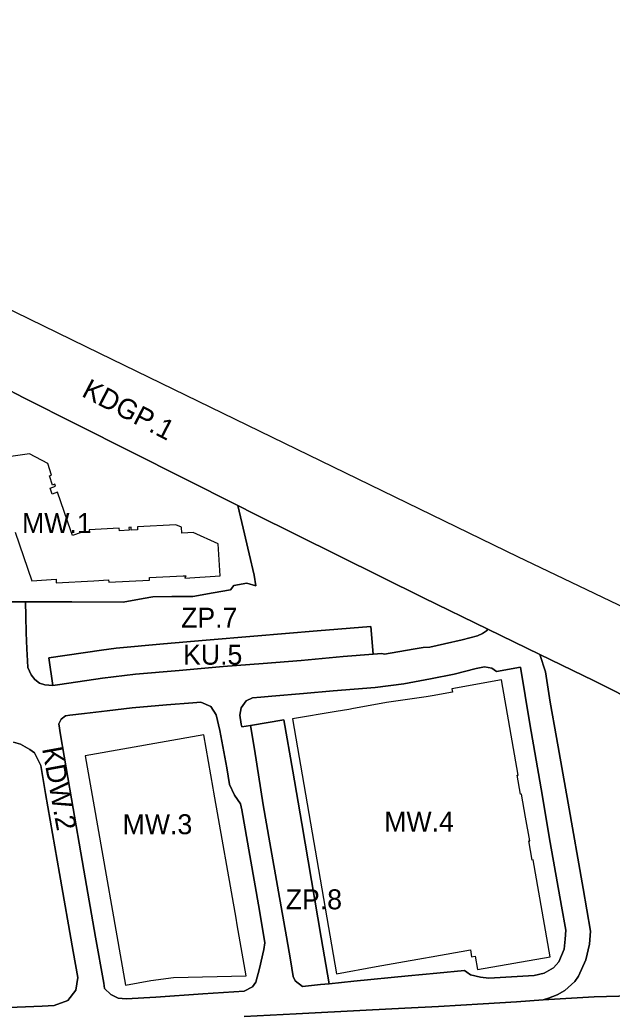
# Model space of a CAD drawing. Extents: x 7429178 to 7430831, y 5550228 to 5551611.
# Drawn here: x 7430079.5 to 7430227.9, y 5551215.2 to 5551464.4 of the extents above; entities that cross this region are included whole.
import ezdxf

# ---------------------------------------------------------------- set-up
doc = ezdxf.new("R2010")
doc.units = 0
for name, color, linetype in [('linie rozgraniczające', 7, 'Continuous'), ('obowiazujace linie zabudowy', 7, 'Continuous'), ('przeznaczenia terenów', 7, 'Continuous')]:
    doc.layers.add(name, color=color, linetype=linetype)

msp = doc.modelspace()

# ---------------------------------------------------------------- linework, layer by layer
at = {"layer": 'linie rozgraniczające'}
for points in [[(7429869.41, 5551487.14), (7429893.85, 5551479.52), (7429909.85, 5551473.11), (7429938.37, 5551459.65), (7430046.47, 5551406.73), (7430099.49, 5551380.97), (7430204.21, 5551330.07), (7430283.32, 5551292.27)], [(7430247.95, 5551286.58), (7430223.25, 5551298.98), (7430220.66, 5551300.21), (7430209.78, 5551305.52), (7430196.74, 5551311.87), (7430180.61, 5551319.73), (7430138.22, 5551340.73), (7430134.15, 5551342.78), (7430093.77, 5551363.12), (7430080.47, 5551369.78), (7430042.2, 5551389.71), (7430023.15, 5551399.37), (7429998.77, 5551410.53), (7429994.07, 5551412.83), (7429989.24, 5551414.99), (7429932.38, 5551440.93), (7429912.77, 5551449.66), (7429902.53, 5551454.19), (7429890.71, 5551458.71), (7429886.5, 5551460.38), (7429882.93, 5551460.46), (7429872.08, 5551460.34)], [(7430051.51, 5551384.86), (7430080.47, 5551369.78), (7430093.77, 5551363.12), (7430134.15, 5551342.78), (7430135.43, 5551337.15), (7430136.97, 5551330.71), (7430138.24, 5551325.41), (7430138.6, 5551322.69), (7430136.34, 5551323.4), (7430133.16, 5551322.82), (7430132.27, 5551321.66), (7430127.96, 5551320.91), (7430122.87, 5551320.03), (7430117.56, 5551319.99), (7430112.83, 5551319.96), (7430110.41, 5551319.53), (7430105.41, 5551318.63), (7430092.52, 5551318.67), (7430080.95, 5551318.71), (7430073.94, 5551318.73)], [(7430073.94, 5551318.73), (7430080.95, 5551318.71), (7430081.01, 5551315.13), (7430081.08, 5551310.89), (7430081.25, 5551306.92), (7430081.38, 5551303.89), (7430081.51, 5551302.27), (7430082.37, 5551300.38), (7430083.26, 5551299.26), (7430084.46, 5551298.36), (7430085.78, 5551297.89), (7430087.77, 5551297.76), (7430089.53, 5551298.02), (7430100.21, 5551299.58), (7430108.49, 5551300.55), (7430119.45, 5551301.49), (7430130.46, 5551302.46), (7430140.5, 5551303.28), (7430149.99, 5551304.04), (7430160.49, 5551304.98), (7430168.02, 5551305.56), (7430170.22, 5551305.73), (7430170.9, 5551305.59), (7430178.03, 5551306.8), (7430180.59, 5551307.23), (7430182.2, 5551307.33), (7430185.89, 5551308.17), (7430190.36, 5551309.2), (7430194.17, 5551310.18), (7430195.45, 5551310.79), (7430196.43, 5551311.47), (7430196.74, 5551311.87), (7430209.78, 5551305.52), (7430211.19, 5551301.16), (7430212.39, 5551293.58), (7430213.96, 5551284.74), (7430216.88, 5551268.25), (7430220.66, 5551246.89), (7430222.45, 5551236.22), (7430222.25, 5551232.98), (7430221.3, 5551229.06), (7430219.5, 5551224.96), (7430218.52, 5551223.58), (7430216.06, 5551221.36), (7430214.13, 5551220.3), (7430211.99, 5551219.46), (7430210.63, 5551218.99), (7430203.93, 5551218.53), (7430195.63, 5551218.02), (7430184.44, 5551217.33), (7430175.97, 5551216.91), (7430166.31, 5551216.43), (7430148.74, 5551215.55), (7430135.73, 5551214.89)], [(7430235.76, 5551220.1), (7430223.44, 5551219.78), (7430210.63, 5551218.99), (7430211.99, 5551219.46), (7430214.13, 5551220.3), (7430216.06, 5551221.36), (7430218.52, 5551223.58), (7430219.5, 5551224.96), (7430221.3, 5551229.06), (7430222.25, 5551232.98), (7430222.45, 5551236.22), (7430220.66, 5551246.89), (7430216.88, 5551268.25), (7430213.96, 5551284.74), (7430212.39, 5551293.58), (7430211.19, 5551301.16), (7430209.78, 5551305.52), (7430220.66, 5551300.21), (7430223.25, 5551298.98), (7430247.95, 5551286.58)], [(7430077.9, 5551283.59), (7430079.64, 5551283.07), (7430081.99, 5551281.75), (7430083.19, 5551280.84), (7430084.72, 5551277.69), (7430085.96, 5551270.66), (7430089.46, 5551250.65), (7430092.88, 5551231.12), (7430094.02, 5551224.62), (7430093.54, 5551221.43), (7430091.54, 5551218.89), (7430088.14, 5551217.61), (7430085.08, 5551217.47), (7430076.73, 5551217.09)], [(7430076.73, 5551217.09), (7430085.08, 5551217.47), (7430088.14, 5551217.61), (7430091.54, 5551218.89), (7430093.54, 5551221.43), (7430094.02, 5551224.62), (7430092.88, 5551231.12), (7430089.46, 5551250.65), (7430085.96, 5551270.66), (7430084.72, 5551277.69), (7430083.19, 5551280.84), (7430081.99, 5551281.75), (7430079.64, 5551283.07), (7430077.9, 5551283.59)], [(7430135.73, 5551214.89), (7430148.74, 5551215.55), (7430166.31, 5551216.43), (7430175.97, 5551216.91), (7430184.44, 5551217.33), (7430195.63, 5551218.02), (7430203.93, 5551218.53), (7430210.63, 5551218.99), (7430223.44, 5551219.78), (7430235.76, 5551220.1)]]:
    msp.add_lwpolyline(points, dxfattribs=at)
for points in [[(7430138.22, 5551340.73), (7430180.61, 5551319.73), (7430196.74, 5551311.87), (7430196.43, 5551311.47), (7430195.45, 5551310.79), (7430194.17, 5551310.18), (7430190.36, 5551309.2), (7430185.89, 5551308.17), (7430182.2, 5551307.33), (7430180.59, 5551307.23), (7430178.03, 5551306.8), (7430170.9, 5551305.59), (7430170.22, 5551305.73), (7430168.02, 5551305.56), (7430167.44, 5551312.53), (7430153.99, 5551311.42), (7430138.15, 5551310.1), (7430126.15, 5551309.09), (7430115.51, 5551308.18), (7430103.64, 5551307.09), (7430099.96, 5551306.62), (7430086.74, 5551304.69), (7430087.77, 5551297.76), (7430085.78, 5551297.89), (7430084.46, 5551298.36), (7430083.26, 5551299.26), (7430082.37, 5551300.38), (7430081.51, 5551302.27), (7430081.38, 5551303.89), (7430081.25, 5551306.92), (7430081.08, 5551310.89), (7430081.01, 5551315.13), (7430080.95, 5551318.71), (7430092.52, 5551318.67), (7430105.41, 5551318.63), (7430110.41, 5551319.53), (7430112.83, 5551319.96), (7430117.56, 5551319.99), (7430122.87, 5551320.03), (7430127.96, 5551320.91), (7430132.27, 5551321.66), (7430133.16, 5551322.82), (7430136.34, 5551323.4), (7430138.6, 5551322.69), (7430138.24, 5551325.41), (7430136.97, 5551330.71), (7430135.43, 5551337.15), (7430134.15, 5551342.78)], [(7430168.02, 5551305.56), (7430160.49, 5551304.98), (7430149.99, 5551304.04), (7430140.5, 5551303.28), (7430130.46, 5551302.46), (7430119.45, 5551301.49), (7430108.49, 5551300.55), (7430100.21, 5551299.58), (7430089.53, 5551298.02), (7430087.77, 5551297.76), (7430086.74, 5551304.69), (7430099.96, 5551306.62), (7430103.64, 5551307.09), (7430115.51, 5551308.18), (7430126.15, 5551309.09), (7430138.15, 5551310.1), (7430153.99, 5551311.42), (7430167.44, 5551312.53)], [(7430157.03, 5551223.06), (7430155.02, 5551234.64), (7430152.58, 5551248.91), (7430150.16, 5551263.14), (7430147.91, 5551276.29), (7430145.68, 5551289.11), (7430137.32, 5551287.74), (7430135.11, 5551287.37), (7430134.99, 5551288.08), (7430134.63, 5551290.32), (7430134.95, 5551292.13), (7430136.22, 5551293.88), (7430137.81, 5551294.68), (7430139.86, 5551294.85), (7430142.64, 5551295.08), (7430150.59, 5551295.75), (7430157.98, 5551296.38), (7430168.49, 5551297.27), (7430175.75, 5551298.17), (7430182.42, 5551299.39), (7430188.33, 5551300.58), (7430193.83, 5551301.99), (7430195.95, 5551302.43), (7430197.75, 5551302.11), (7430198.94, 5551301.27), (7430204.94, 5551302.35), (7430207.29, 5551288.18), (7430210.1, 5551271.86), (7430212.39, 5551258.46), (7430215.22, 5551242.46), (7430216.3, 5551236.5), (7430216.15, 5551234.25), (7430215.91, 5551231.74), (7430214.53, 5551228.58), (7430213.19, 5551227.07), (7430210.86, 5551225.7), (7430208.38, 5551225.15), (7430202.72, 5551224.8), (7430197, 5551224.45), (7430194.94, 5551224.69), (7430192.4, 5551225.32), (7430191.53, 5551225.94), (7430190.92, 5551226.38), (7430184, 5551225.73), (7430176.82, 5551225.03), (7430163.17, 5551223.67)], [(7430136.22, 5551293.88), (7430134.95, 5551292.13), (7430134.63, 5551290.32), (7430134.99, 5551288.08), (7430135.11, 5551287.37), (7430137.32, 5551287.74), (7430138.26, 5551281.82), (7430140.46, 5551267.87), (7430142.16, 5551258.38), (7430144.34, 5551246.03), (7430146.29, 5551234.81), (7430147.28, 5551229.01), (7430147.98, 5551224.86), (7430148.51, 5551223.75), (7430150.35, 5551222.4), (7430154.84, 5551222.85), (7430157.03, 5551223.06), (7430163.17, 5551223.67), (7430176.82, 5551225.03), (7430184, 5551225.73), (7430190.92, 5551226.38), (7430191.53, 5551225.94), (7430192.4, 5551225.32), (7430194.94, 5551224.69), (7430197, 5551224.45), (7430202.72, 5551224.8), (7430208.38, 5551225.15), (7430210.86, 5551225.7), (7430213.19, 5551227.07), (7430214.53, 5551228.58), (7430215.91, 5551231.74), (7430216.15, 5551234.25), (7430216.3, 5551236.5), (7430215.22, 5551242.46), (7430212.39, 5551258.46), (7430210.1, 5551271.86), (7430207.29, 5551288.18), (7430204.94, 5551302.35), (7430198.94, 5551301.27), (7430197.75, 5551302.11), (7430195.95, 5551302.43), (7430193.83, 5551301.99), (7430188.33, 5551300.58), (7430182.42, 5551299.39), (7430175.75, 5551298.17), (7430168.49, 5551297.27), (7430157.98, 5551296.38), (7430150.59, 5551295.75), (7430142.64, 5551295.08), (7430139.86, 5551294.85), (7430137.81, 5551294.68)], [(7430113.57, 5551219.73), (7430106.11, 5551219.25), (7430104.14, 5551219.47), (7430102.31, 5551220.36), (7430100.75, 5551221.84), (7430100.51, 5551223.2), (7430098.49, 5551234.74), (7430095.56, 5551251.5), (7430092.43, 5551269.36), (7430089.7, 5551285.42), (7430089.29, 5551288.1), (7430089.89, 5551289.29), (7430090.95, 5551290.15), (7430092, 5551290.3), (7430095.73, 5551290.73), (7430101.38, 5551291.4), (7430107.66, 5551292.17), (7430116.27, 5551292.89), (7430122.87, 5551293.44), (7430124.87, 5551293.6), (7430127.32, 5551292.47), (7430128.72, 5551290.41), (7430129.65, 5551286.47), (7430131.35, 5551277.12), (7430132.06, 5551272.97), (7430133.27, 5551270.3), (7430134.78, 5551268.1), (7430135.1, 5551266.57), (7430137.11, 5551255.13), (7430139.55, 5551241.43), (7430140.92, 5551233.28), (7430140.64, 5551231.63), (7430139.59, 5551226.83), (7430138.59, 5551223.47), (7430137.8, 5551222.25), (7430135.69, 5551221.16), (7430133.13, 5551220.99), (7430125.38, 5551220.49)], [(7430129.65, 5551286.47), (7430128.72, 5551290.41), (7430127.32, 5551292.47), (7430124.87, 5551293.6), (7430122.87, 5551293.44), (7430116.27, 5551292.89), (7430107.66, 5551292.17), (7430101.38, 5551291.4), (7430095.73, 5551290.73), (7430092, 5551290.3), (7430090.95, 5551290.15), (7430089.89, 5551289.29), (7430089.29, 5551288.1), (7430089.7, 5551285.42), (7430092.43, 5551269.36), (7430095.56, 5551251.5), (7430098.49, 5551234.74), (7430100.51, 5551223.2), (7430100.75, 5551221.84), (7430102.31, 5551220.36), (7430104.14, 5551219.47), (7430106.11, 5551219.25), (7430113.57, 5551219.73), (7430125.38, 5551220.49), (7430133.13, 5551220.99), (7430135.69, 5551221.16), (7430137.8, 5551222.25), (7430138.59, 5551223.47), (7430139.59, 5551226.83), (7430140.64, 5551231.63), (7430140.92, 5551233.28), (7430139.55, 5551241.43), (7430137.11, 5551255.13), (7430135.1, 5551266.57), (7430134.78, 5551268.1), (7430133.27, 5551270.3), (7430132.06, 5551272.97), (7430131.35, 5551277.12)], [(7430157.03, 5551223.06), (7430154.84, 5551222.85), (7430150.35, 5551222.4), (7430148.51, 5551223.75), (7430147.98, 5551224.86), (7430147.28, 5551229.01), (7430146.29, 5551234.81), (7430144.34, 5551246.03), (7430142.16, 5551258.38), (7430140.46, 5551267.87), (7430138.26, 5551281.82), (7430137.32, 5551287.74), (7430145.68, 5551289.11), (7430147.91, 5551276.29), (7430150.16, 5551263.14), (7430152.58, 5551248.91), (7430155.02, 5551234.64)]]:
    msp.add_lwpolyline(points, close=True, dxfattribs=at)
at = {"layer": 'obowiazujace linie zabudowy'}
for points in [[(7430081.92, 5551355.76), (7430072.5, 5551354.42)], [(7430078.3, 5551336.11), (7430082.51, 5551323.99), (7430088.59, 5551324.35), (7430088.63, 5551323.42), (7430098.02, 5551323.97), (7430101.72, 5551324.16), (7430101.77, 5551323.58), (7430111.97, 5551324.12), (7430111.97, 5551324.76), (7430120.41, 5551325.22), (7430121.05, 5551325.22), (7430120.85, 5551324.64), (7430129.69, 5551325.17), (7430129.22, 5551333.2), (7430122.93, 5551336.06), (7430121.61, 5551335.96), (7430120.06, 5551335.86), (7430119.99, 5551337.41), (7430118.62, 5551337.99), (7430108.97, 5551337.44), (7430109, 5551336.71), (7430107.41, 5551336.65), (7430107.38, 5551337.36), (7430106.84, 5551337.33), (7430106.89, 5551336.6), (7430104.44, 5551336.44), (7430104.4, 5551337.15), (7430096.91, 5551336.72), (7430096.94, 5551336.15), (7430094.88, 5551336.05), (7430092.72, 5551335.28), (7430092.31, 5551336.46), (7430088.97, 5551346.13), (7430087.64, 5551345.64), (7430087.11, 5551347.17), (7430088.43, 5551347.64), (7430088.26, 5551348.13), (7430087.7, 5551347.92), (7430086.89, 5551350.23), (7430087.45, 5551350.41), (7430086.52, 5551353.3), (7430081.92, 5551355.76)], [(7430206.22, 5551264.73), (7430205.2, 5551270.53), (7430204.95, 5551270.49), (7430204.11, 5551275.28), (7430204.35, 5551275.32), (7430200.17, 5551299.13), (7430187.72, 5551296.94), (7430187.87, 5551296.05), (7430182.81, 5551295.16), (7430181.31, 5551294.9), (7430171.41, 5551293.46), (7430170.03, 5551293.21), (7430163.1, 5551291.98), (7430161.94, 5551291.77), (7430158.75, 5551291.23), (7430147.82, 5551289.36), (7430158.85, 5551225.51), (7430168.79, 5551227.33), (7430173.06, 5551228.11), (7430174.47, 5551228.36), (7430180.64, 5551229.43), (7430182.58, 5551229.77), (7430192.39, 5551231.54), (7430192.69, 5551229.81), (7430193.59, 5551229.97), (7430194.18, 5551226.64), (7430212.35, 5551229.82), (7430208.09, 5551254.09), (7430207.85, 5551254.04), (7430207, 5551258.8), (7430207.25, 5551258.84), (7430206.22, 5551264.73)], [(7430133.98, 5551237.84), (7430133.69, 5551239.51), (7430128.14, 5551270.99), (7430127.96, 5551272.03), (7430125.61, 5551285.4), (7430095.87, 5551280.16), (7430097.9, 5551268.8), (7430105.95, 5551222.67), (7430112.33, 5551223.86), (7430117.98, 5551224.58), (7430136.22, 5551225.01), (7430133.98, 5551237.84)]]:
    msp.add_lwpolyline(points, dxfattribs=at)

# ---------------------------------------------------------------- texts
at = {"layer": 'przeznaczenia terenów'}
for s, rotation, p in [('KDGP.1', 332.4573, (7430094.74, 5551370.3)), ('KDW.2', 280.3544, (7430085.05, 5551281.95))]:
    msp.add_text(s, height=5, rotation=rotation, dxfattribs=at).set_placement(p)
for s, p in [('MW.1', (7430080.05, 5551335.9)), ('ZP.7', (7430119.89, 5551312.22)), ('KU.5', (7430120.38, 5551302.95)), ('MW.3', (7430105.25, 5551260.5)), ('MW.4', (7430170.8, 5551261.16)), ('ZP.8', (7430146.11, 5551241.69))]:
    msp.add_text(s, height=5, dxfattribs=at).set_placement(p)

doc.saveas('drawing.dxf')
